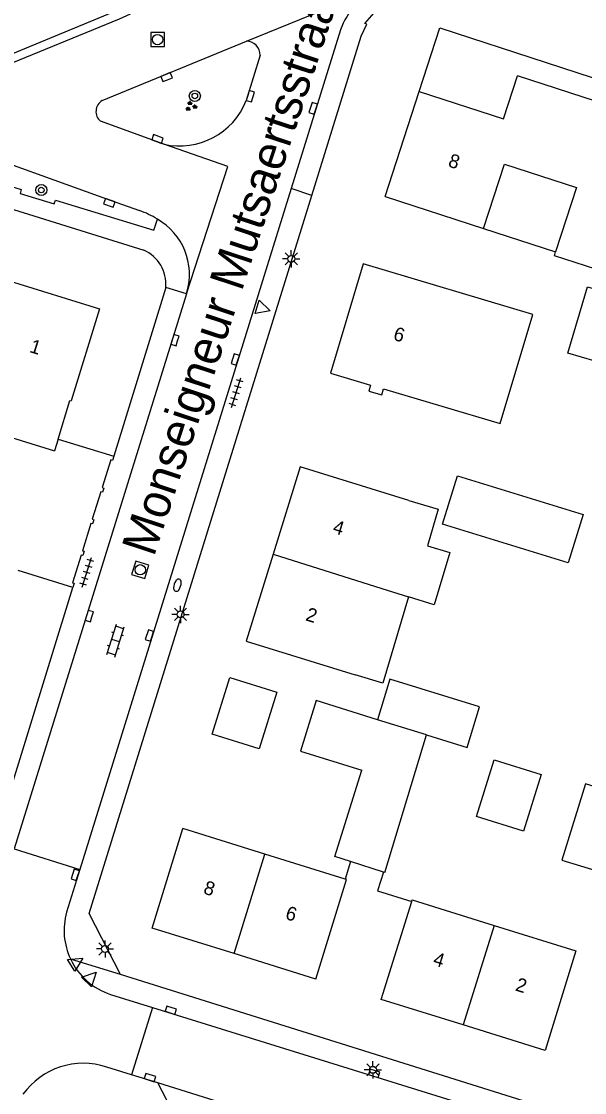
# Model space of a CAD drawing. Extents: x 136000 to 138005, y 398500 to 400500.
# Drawn here: x 137397.1 to 137437.9, y 399055.6 to 399133.2 of the extents above; entities that cross this region are included whole.
import ezdxf

# ---------------------------------------------------------------- set-up
doc = ezdxf.new("R2010")
doc.units = 0
for name, color, linetype in [('gg-afsc-erfafscheiding', 7, 'Continuous'), ('gg-afsc-muur', 7, 'Continuous'), ('gg-anno-huisnummerreeks BGT', 7, 'Continuous'), ('gg-anno-openbare ruimte label', 7, 'Continuous'), ('gg-bbg-bijgebouw', 7, 'Continuous'), ('gg-bbg-gedigitaliseerde bebouwing', 7, 'Continuous'), ('gg-bbg-gedigitaliseerde bijgebouw', 7, 'Continuous'), ('gg-bbg-hoofdgebouw', 7, 'Continuous'), ('gg-bbg-luifel en loopbrug', 7, 'Continuous'), ('gg-bbg-tussenscheiding', 7, 'Continuous'), ('gg-knt-verharding', 7, 'Continuous'), ('gt-grn-groengrens', 7, 'Continuous'), ('gt-grn-weggrens', 7, 'Continuous'), ('gt-symb-boom', 7, 'Continuous'), ('gt-symb-brandkraan', 7, 'Continuous'), ('gt-symb-groenvak', 7, 'Continuous'), ('gt-symb-klinker verharding', 7, 'Continuous'), ('gt-symb-kolk', 7, 'Continuous'), ('gt-symb-lichtmast', 7, 'Continuous'), ('gt-symb-rioolschacht', 7, 'Continuous'), ('gt-symb-tegel verharding', 7, 'Continuous'), ('gt-symb-waterafsluiter', 7, 'Continuous')]:
    doc.layers.add(name, color=color, linetype=linetype)

# ---------------------------------------------------------------- blocks, each defined once
blk = doc.blocks.new('gt0-RS')
at = {"layer": 'gt-symb-rioolschacht'}
blk.add_lwpolyline([(-0.5, -0.5), (0.5, -0.5), (0.5, 0.5), (-0.5, 0.5)], close=True, dxfattribs=at)
blk.add_circle((0, 0), 0.375, dxfattribs=at)
blk = doc.blocks.new('gt0-BOOM')
at = {"layer": 'gt-symb-boom'}
for radius in [0.4, 0.2]:
    blk.add_circle((0, 0), radius, dxfattribs=at)
blk = doc.blocks.new('gt0-KOLK')
at = {"layer": 'gt-symb-kolk'}
blk.add_lwpolyline([(0, 0), (0.375, 0), (0.375, 0.4), (-0.375, 0.4), (-0.375, 0), (0, 0)], dxfattribs=at)
blk = doc.blocks.new('gt0-GRVAK')
at = {"layer": 'gt-symb-groenvak'}
for p, q in [((-0.11, 0.189), (-0.228, 0.24)), ((-0.182, 0.153), (0.088, 0.153)), ((-0.091, 0.211), (-0.156, 0.322)), ((-0.047, 0.214), (-0.047, 0.393)), ((-0.004, 0.211), (0.061, 0.322)), ((0.015, 0.189), (0.133, 0.24)), ((0.262, -0.052), (0.197, 0.059)), ((0.305, -0.049), (0.305, 0.13)), ((0.349, -0.052), (0.414, 0.059)), ((-0.245, -0.228), (-0.363, -0.177)), ((-0.318, -0.264), (-0.047, -0.264)), ((-0.226, -0.206), (-0.291, -0.095)), ((-0.183, -0.203), (-0.183, -0.024)), ((-0.139, -0.206), (-0.074, -0.095)), ((-0.12, -0.228), (-0.002, -0.177)), ((0.243, -0.074), (0.125, -0.023)), ((0.17, -0.11), (0.441, -0.11)), ((0.368, -0.074), (0.486, -0.023))]:
    blk.add_line(p, q, dxfattribs=at)
blk = doc.blocks.new('gt0-TEG1')
at = {"layer": 'gt-symb-tegel verharding'}
for p, q in [((-1.125, 0), (1.125, 0)), ((-0.9, -0.25), (-0.9, 0.25)), ((-0.45, -0.25), (-0.45, 0.25)), ((0, -0.25), (0, 0.25)), ((0.45, -0.25), (0.45, 0.25)), ((0.9, -0.25), (0.9, 0.25))]:
    blk.add_line(p, q, dxfattribs=at)
blk = doc.blocks.new('gt0-WAFSL')
at = {"layer": 'gt-symb-waterafsluiter'}
for p, q in [((-0.5, -0.333), (0, 0.667)), ((0, 0.667), (0.5, -0.333)), ((0.5, -0.333), (-0.5, -0.333))]:
    blk.add_line(p, q, dxfattribs=at)
blk = doc.blocks.new('gt0-LMAST')
at = {"layer": 'gt-symb-lichtmast'}
for p, q in [((-0.182, 0.173), (-0.447, 0.438)), ((-0.005, 0.246), (-0.005, 0.621)), ((0.172, 0.173), (0.437, 0.438)), ((-0.255, -0.004), (-0.63, -0.004)), ((-0.182, -0.181), (-0.447, -0.446)), ((-0.005, -0.254), (-0.005, -0.629)), ((0.437, -0.446), (0.172, -0.181)), ((0.245, -0.004), (0.62, -0.004))]:
    blk.add_line(p, q, dxfattribs=at)
blk.add_circle((-0.005, -0.004), 0.25, dxfattribs=at)
blk = doc.blocks.new('gt0-KL1')
at = {"layer": 'gt-symb-klinker verharding'}
for p, q in [((-1.15, 0.3), (1.15, 0.3)), ((-1, -0.3), (-1, 0.3)), ((-0.5, 0.3), (-0.5, 0.45)), ((0, -0.3), (0, 0.3)), ((0.5, 0.3), (0.5, 0.45)), ((1, -0.3), (1, 0.3)), ((-1.15, -0.3), (1.15, -0.3)), ((-0.5, -0.45), (-0.5, -0.3)), ((0.5, -0.45), (0.5, -0.3))]:
    blk.add_line(p, q, dxfattribs=at)
blk = doc.blocks.new('gt0-BR')
at = {"layer": 'gt-symb-brandkraan'}
for centre, radius, start, end in [((-0.244, 0), 0.206, 107.56694, 252.43307), ((0.599, -2.664), 3, 106.89205, 107.56694), ((0, -0.691), 0.938, 73.10799, 106.89205), ((-0.599, -2.664), 3, 72.43309, 73.10799), ((0.244, 0), 0.206, 287.56695, 72.43309), ((0.599, 2.664), 3, 252.43307, 253.10797), ((0, 0.691), 0.938, 253.10797, 286.89206), ((-0.599, 2.664), 3, 286.89206, 287.56695)]:
    blk.add_arc(centre, radius, start, end, dxfattribs=at)

msp = doc.modelspace()

# ---------------------------------------------------------------- linework, layer by layer
at = {"layer": 'gg-afsc-erfafscheiding'}
for p, q in [((137420.955, 399072.368), (137420.572, 399071.106)), ((137422.907, 399070.264), (137425.385, 399069.48))]:
    msp.add_line(p, q, dxfattribs=at)
at = {"layer": 'gg-afsc-muur'}
for p, q in [((137399.757, 399102.983), (137403.782, 399101.748)), ((137400.814, 399092.24), (137396.862, 399093.474)), ((137423.333, 399071.615), (137422.907, 399070.264))]:
    msp.add_line(p, q, dxfattribs=at)
msp.add_lwpolyline([(137403.782, 399101.748), (137403.687, 399101.443), (137403.572, 399101.478), (137402.946, 399099.474), (137403.061, 399099.438), (137402.966, 399099.132), (137402.851, 399099.168), (137402.231, 399097.183), (137402.345, 399097.147), (137402.25, 399096.841), (137402.136, 399096.877), (137401.516, 399094.892), (137401.63, 399094.856), (137401.535, 399094.551), (137401.421, 399094.586), (137400.795, 399092.582), (137400.91, 399092.546), (137400.814, 399092.24)], dxfattribs=at)
at = {"layer": 'gg-bbg-bijgebouw'}
for p, q in [((137420.955, 399072.368), (137419.816, 399072.729)), ((137423.333, 399071.615), (137420.955, 399072.368)), ((137423.43, 399071.584), (137423.333, 399071.615))]:
    msp.add_line(p, q, dxfattribs=at)
msp.add_lwpolyline([(137414.32, 399080.541), (137410.91, 399081.601), (137412.19, 399085.711), (137415.6, 399084.641)], dxfattribs=at)
at = {"layer": 'gg-bbg-gedigitaliseerde bebouwing'}
for p, q in [((137442.358, 399126.275), (137433.06, 399129.311)), ((137423.45, 399120.561), (137430.592, 399118.249)), ((137393.002, 399104.134), (137399.501, 399102.135)), ((137425.186, 399098.538), (137417.29, 399100.971)), ((137413.38, 399088.341), (137421.276, 399085.908)), ((137425.42, 399069.593), (137431.37, 399067.743))]:
    msp.add_line(p, q, dxfattribs=at)
for points in [[(137430.592, 399118.249), (137432.108, 399122.907), (137437.334, 399121.206), (137435.818, 399116.548)], [(137441.039, 399119.809), (137439.489, 399115.046), (137435.728, 399116.27), (137435.818, 399116.548)], [(137431.793, 399104.109), (137434.161, 399112.02), (137421.86, 399115.69)], [(137423.22, 399106.191), (137423.348, 399106.622), (137431.793, 399104.109)], [(137425.186, 399098.538), (137427.305, 399097.912), (137426.519, 399095.253), (137428.141, 399094.774), (137427.021, 399090.984), (137425.145, 399091.557)], [(137425.145, 399091.557), (137423.3, 399085.31), (137421.276, 399085.908)], [(137431.37, 399067.743), (137437.292, 399065.902), (137435.05, 399058.691)]]:
    msp.add_lwpolyline(points, dxfattribs=at)
at = {"layer": 'gg-bbg-gedigitaliseerde bijgebouw'}
for p, q in [((137445.181, 399106.705), (137436.715, 399109.205)), ((137415.6, 399084.641), (137414.32, 399080.541)), ((137422.9, 399082.655), (137418.45, 399084.037)), ((137423.43, 399071.584), (137426.455, 399081.558)), ((137419.816, 399072.729), (137421.762, 399078.994))]:
    msp.add_line(p, q, dxfattribs=at)
for points in [[(137436.715, 399109.205), (137438.133, 399114.009), (137446.6, 399111.508)], [(137427.629, 399096.818), (137428.71, 399100.324), (137437.81, 399097.521), (137436.73, 399094.015), (137427.629, 399096.818)], [(137426.455, 399081.558), (137429.402, 399080.648), (137430.306, 399083.575), (137423.81, 399085.582), (137422.9, 399082.655)], [(137418.45, 399084.037), (137417.313, 399080.376), (137421.762, 399078.994)], [(137433.496, 399074.58), (137430.086, 399075.64), (137431.366, 399079.75), (137434.776, 399078.68), (137433.496, 399074.58)], [(137441.214, 399071.379), (137442.484, 399076.608), (137437.974, 399078), (137436.272, 399072.487), (137441.12, 399070.99)]]:
    msp.add_lwpolyline(points, dxfattribs=at)
at = {"layer": 'gg-bbg-hoofdgebouw'}
for p, q in [((137423.45, 399120.561), (137425.93, 399128.18)), ((137399.757, 399102.983), (137399.501, 399102.135)), ((137417.29, 399100.971), (137415.335, 399094.656)), ((137415.335, 399094.656), (137413.38, 399088.341)), ((137414.739, 399072.917), (137408.8, 399074.761)), ((137420.572, 399071.106), (137414.739, 399072.917)), ((137423.18, 399062.381), (137425.385, 399069.48)), ((137425.385, 399069.48), (137425.42, 399069.593)), ((137418.44, 399063.861), (137412.505, 399065.701)), ((137429.11, 399060.538), (137423.18, 399062.381)), ((137435.05, 399058.691), (137429.11, 399060.538))]:
    msp.add_line(p, q, dxfattribs=at)
for points in [[(137425.93, 399128.18), (137432.04, 399126.191), (137433.06, 399129.311)], [(137421.86, 399115.69), (137419.49, 399107.77), (137422.41, 399106.901), (137422.28, 399106.47), (137423.22, 399106.191)], [(137396.21, 399114.446), (137402.75, 399112.431), (137400.697, 399105.749)], [(137399.757, 399102.983), (137400.601, 399105.778), (137400.697, 399105.749)], [(137412.505, 399065.701), (137406.57, 399067.541), (137408.8, 399074.761)], [(137418.44, 399063.861), (137420.658, 399071.079), (137420.572, 399071.106)]]:
    msp.add_lwpolyline(points, dxfattribs=at)
at = {"layer": 'gg-bbg-luifel en loopbrug'}
msp.add_line((137430.592, 399118.249), (137435.818, 399116.548), dxfattribs=at)
msp.add_lwpolyline([(137425.93, 399128.18), (137427.425, 399132.773), (137442.84, 399127.755), (137442.358, 399126.275)], dxfattribs=at)
at = {"layer": 'gg-bbg-tussenscheiding'}
for p, q in [((137415.335, 399094.656), (137423.208, 399092.148)), ((137423.208, 399092.148), (137425.145, 399091.557)), ((137426.455, 399081.558), (137422.9, 399082.655)), ((137412.505, 399065.701), (137414.739, 399072.917)), ((137431.37, 399067.743), (137429.11, 399060.538))]:
    msp.add_line(p, q, dxfattribs=at)
at = {"layer": 'gg-knt-verharding'}
for p, q in [((137420.22, 399132.641), (137416.65, 399121.146)), ((137402.94, 399127.509), (137413.4, 399131.811)), ((137414.389, 399130.811), (137413.39, 399127.51)), ((137407.422, 399124.348), (137402.83, 399126.011)), ((137391.116, 399121.299), (137405.96, 399116.68)), ((137416.65, 399121.146), (137401.32, 399071.791)), ((137409.061, 399113.511), (137396.556, 399073.287)), ((137407.55, 399113.981), (137403.782, 399101.748)), ((137409.095, 399113.624), (137409.061, 399113.511)), ((137396.556, 399073.287), (137401.32, 399071.791)), ((137401.32, 399071.791), (137400.36, 399068.701)), ((137475.32, 399041.941), (137404.27, 399064.191)), ((137403.558, 399062.75), (137406.598, 399061.805)), ((137406.598, 399061.805), (137405.074, 399056.927)), ((137405.074, 399056.927), (137403.277, 399057.487)), ((137406.986, 399056.332), (137405.074, 399056.927)), ((137447.609, 399043.689), (137406.986, 399056.332))]:
    msp.add_line(p, q, dxfattribs=at)
for points in [[(137418.14, 399120.629), (137421.72, 399132.17), (137422.14, 399133.04), (137421.99, 399133.11), (137422.83, 399134.06), (137423.69, 399134.521), (137459.313, 399149.2)], [(137395.447, 399129.859), (137404.207, 399133.444), (137405.009, 399133.807)], [(137392.124, 399124.395), (137403.534, 399120.292), (137405.647, 399119.543)], [(137391.567, 399122.75), (137397.08, 399121.062), (137396.998, 399120.793), (137399.476, 399120.03), (137399.56, 399120.302), (137406.693, 399118.133), (137406.947, 399118.921)], [(137404.27, 399064.191), (137402, 399068.601), (137418.14, 399120.629)], [(137389.9, 399068.651), (137394.31, 399071.221), (137400.814, 399092.24)], [(137406.598, 399061.805), (137467.194, 399042.977), (137472.545, 399041.022)], [(137423.325, 399049.137), (137408.273, 399053.876), (137406.986, 399056.332)]]:
    msp.add_lwpolyline(points, dxfattribs=at)
for centre, radius, start, end in [((137425.594, 399130.653), 5.73, 117.82168, 159.7012), ((137413.402, 399130.824), 0.987, 359.23482, 90.13145), ((137403.419, 399126.721), 0.922, 121.2743, 230.32618), ((137408.549, 399129.434), 5.21, 257.50884, 338.32275), ((137403.611, 399113.618), 6.265, 57.82606, 71.03529), ((137404.665, 399114.912), 4.613, 343.78955, 60.3568), ((137404.894, 399114.234), 2.668, 354.55721, 66.44807), ((137405.076, 399067.403), 4.892, 164.61075, 205.27763), ((137405.078, 399067.4), 4.892, 205.23894, 251.89677), ((137401.589, 399052.357), 5.4, 71.78932, 144.28045)]:
    msp.add_arc(centre, radius, start, end, dxfattribs=at)
at = {"layer": 'gt-grn-groengrens'}
msp.add_line((137395.121, 399130.37), (137404.054, 399134.062), dxfattribs=at)
at = {"layer": 'gt-grn-weggrens'}
for p, q in [((137413.4, 399131.811), (137422.92, 399135.721)), ((137412.055, 399122.74), (137407.422, 399124.348)), ((137409.061, 399113.511), (137412.055, 399122.74)), ((137418.14, 399120.629), (137416.65, 399121.146)), ((137409.061, 399113.511), (137407.55, 399113.981)), ((137404.27, 399064.191), (137400.653, 399065.314))]:
    msp.add_line(p, q, dxfattribs=at)

# ---------------------------------------------------------------- block references
at = {"layer": 'gt-symb-boom'}
for p in [(137409.665, 399127.85), (137398.531, 399121.031)]:
    msp.add_blockref('gt0-BOOM', p, dxfattribs=at)
at = {"layer": 'gt-symb-brandkraan', "rotation": 72.90569440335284}
msp.add_blockref('gt0-BR', (137408.4, 399092.4), dxfattribs=at)
at = {"layer": 'gt-symb-groenvak'}
msp.add_blockref('gt0-GRVAK', (137409.364, 399127.096), dxfattribs=at)
at = {"layer": 'gt-symb-klinker verharding', "rotation": 72.77930062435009}
msp.add_blockref('gt0-KL1', (137403.922, 399088.381), dxfattribs=at)
at = {"layer": 'gt-symb-kolk'}
for p, rotation in [((137407.69, 399129.029), 22.33338843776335), ((137413.504, 399127.887), -106.8399115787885), ((137418.433, 399126.888), 72.34847766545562), ((137406.888, 399124.541), -19.93904791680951), ((137403.534, 399120.292), 160.47536575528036), ((137408.417, 399110.095), 72.72457972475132), ((137412.783, 399108.693), 72.72457972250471), ((137402.203, 399090.101), 72.72457972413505), ((137406.568, 399088.697), 72.72457972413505), ((137401.184, 399071.356), 72.72457972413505), ((137407.867, 399061.412), -17.275420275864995), ((137406.351, 399056.535), -17.275420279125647), ((137422.605, 399056.832), -17.275420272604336)]:
    msp.add_blockref('gt0-KOLK', p, dxfattribs=dict(at, rotation=rotation))
at = {"layer": 'gt-symb-lichtmast'}
for p in [(137416.659, 399116.049), (137408.633, 399090.287), (137403.157, 399066.045), (137422.578, 399057.287)]:
    msp.add_blockref('gt0-LMAST', p, dxfattribs=at)
at = {"layer": 'gt-symb-rioolschacht'}
msp.add_blockref('gt0-RS', (137406.968, 399131.935), dxfattribs=at)
at = {"layer": 'gt-symb-rioolschacht', "rotation": 72.7245797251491}
msp.add_blockref('gt0-RS', (137405.71, 399093.515), dxfattribs=at)
at = {"layer": 'gt-symb-tegel verharding', "rotation": 72.77930062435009}
for p in [(137412.655, 399106.34), (137401.838, 399093.324)]:
    msp.add_blockref('gt0-TEG1', p, dxfattribs=at)
at = {"layer": 'gt-symb-waterafsluiter'}
for p, rotation in [((137414.497, 399112.466), -106.67729393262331), ((137400.979, 399065.028), -57.91563845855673), ((137402.042, 399063.894), -44.35170201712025)]:
    msp.add_blockref('gt0-WAFSL', p, dxfattribs=dict(at, rotation=rotation))

# ---------------------------------------------------------------- texts
at = {"layer": 'gg-anno-huisnummerreeks BGT'}
for s, rotation, p in [('8', 341.9, (137427.962, 399122.757)), ('6', 343.3, (137423.986, 399110.195)), ('1', 342.9, (137397.625, 399109.301)), ('4', 342.8, (137419.597, 399096.211)), ('2', 342.8, (137417.633, 399089.865)), ('8', 342.8, (137410.225, 399070.072)), ('6', 342.8, (137416.16, 399068.232)), ('4', 342.7, (137426.87, 399064.901)), ('2', 342.7, (137432.835, 399063.046))]:
    msp.add_text(s, height=1, rotation=rotation, dxfattribs=at).set_placement(p)
at = {"layer": 'gg-anno-openbare ruimte label'}
msp.add_text('Monseigneur Mutsaertsstraat', height=2.5, rotation=71.7, dxfattribs=at).set_placement((137406.695, 399094.394))

doc.saveas('drawing.dxf')
